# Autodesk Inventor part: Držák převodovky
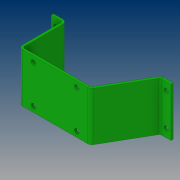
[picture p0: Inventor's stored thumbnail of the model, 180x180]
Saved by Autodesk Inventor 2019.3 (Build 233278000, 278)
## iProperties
Created: 2019-02
Part Number: Držák převodovky
Material: Ocel, pozinkovaná
Document SubType Name: Plech
Designer: B-hon
Density: 7.85 g/cm^3
Sheet Metal Rule: Výchozí_mm
Appearance: Tmavě zelená
Author: B-hon
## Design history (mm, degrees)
node "Plocha2"
  sketch "Náčrt1"
    geometry: L1 (0, 0)-(132.7, 0); L2 (132.7, 0)-(132.7, 90); L3 (132.7, 90)-(0, 90); L4 (0, 90)-(0, 0)
    constraints: 8 end point, 2 parallel, 1 horizontal, 1 perpendicular
    dimensions: "d0" = 132.7 distance of L3.end L2.end; "d1" = 90 distance of L2.end L1.end
node "Obruba5"
node "Obruba6"
node "Obruba7"
node "Obruba8"
sketch "Náčrt14"
  geometry: L1 (17, 90)-(0, 90) reference; L2 (0, 90)-(0, 0) reference; L3 (17, 0)-(0, 0) reference; 3 further points
  dimensions: "d117" = 15 distance from line of L1 point (8.5, 75); "d118" = 8.5 distance from line of L2 point (8.5, 75); "d119" = 15 distance from line of L3 point (8.5, 15); "d120" = 8.5 distance from line of L2 point (8.5, 15)
hole "Díra4" sketch "Náčrt14" at (8.5, 15), (8.5, 75) diameter "d121" = 8.5; stored, may be unused: countersink angle "d125" = 90 deg, drill point angle "d127" = 118 deg; dims "d122" = 6, "d123" = 4, "d124" = 2, "d126" = 4 (= Tloušťka)
sketch "Náčrt15"
  geometry: L1 (-17.381, 90)-(0, 90) reference; L2 (0, 0)-(0, 90) reference; L3 (-17.381, 0)-(0, 0) reference; 3 further points
  dimensions: "d128" = 15 distance from line of L1 point (-8.5, 75); "d129" = 8.5 distance from line of L2 point (-8.5, 75); "d130" = 8.5 distance from line of L2 point (-8.5, 15); "d131" = 15 distance from line of L3 point (-8.5, 15)
hole "Díra5" sketch "Náčrt15" at (-8.5, 75), (-8.5, 15) diameter "d132" = 8.5; stored, may be unused: countersink angle "d136" = 90 deg, drill point angle "d138" = 118 deg; dims "d133" = 6, "d134" = 4, "d135" = 2, "d137" = 4 (= Tloušťka)
sketch "Náčrt16"
  geometry: L1 (28, 80)-(108, 80); L2 (108, 80)-(108, 10); L3 (108, 10)-(28, 10); L4 (28, 10)-(28, 80); L5 (8, 90)-(128.081, 90) reference; L6 (8, 90)-(8, 0) reference; 5 further points
  constraints: 8 end point, 4 coincident, 2 parallel, 1 horizontal, 1 perpendicular
  dimensions: "d139" = 80 distance of L2.end L3.end; "d140" = 70 distance of L1.end L2.end; "d141" = 10 distance between parallel lines of L1 L5; "d142" = 20 distance between parallel lines of L6 L4
hole "Díra6" sketch "Náčrt16" at (28, 80), (108, 80), (108, 10), (28, 10) diameter "d143" = 8.5; stored, may be unused: countersink angle "d147" = 90 deg, drill point angle "d149" = 118 deg; dims "d144" = 6, "d145" = 4, "d146" = 2, "d148" = 4 (= Tloušťka)
node "Těleso2"
feature "Deska6" dims "d76" = 4 (= Tloušťka)
sketch "Náčrt10"
  geometry: L1 through (45, 0) direction (-1, 9.36e-35); L2 through (0, -43) direction (-3.91e-32, -1); L3 (0, -86)-(90, -86); L4 (90, -86)-(90, 0)
  constraints: 6 end point, 1 horizontal, 1 perpendicular, 1 vertical
feature "Deska7" dims "d76" = 4 (= Tloušťka), "d77" = 4 (= ŠířkaVýštipu), "d78" = 2 (= HloubkaVýštipu), "d79" = 8 (= MinimálníZbytek), "d80" = 4 (= PřechodovýPoloměr), "d81" = 86, "d82" = 90 deg, "d83" = 4 (= PoloměrOhybu), "d84" = 16 (= VelikostRohovéhoVýštipu), "d85" = 4 (= VelikostMezery), "d86" = 4 (= VelikostJacobihoPoloměru), "MezeraVystřižení" = 0.01
feature "Ohyb5" dims "d76" = 4 (= Tloušťka), "d77" = 4 (= ŠířkaVýštipu), "d78" = 2 (= HloubkaVýštipu), "d79" = 8 (= MinimálníZbytek), "d80" = 4 (= PřechodovýPoloměr), "d81" = 86, "d82" = 90 deg, "d83" = 4 (= PoloměrOhybu), "MezeraVystřižení" = 0.01
feature "Roh5" dims "d81" = 86, "d82" = 90 deg, "d84" = 16 (= VelikostRohovéhoVýštipu), "d85" = 4 (= VelikostMezery), "d86" = 4 (= VelikostJacobihoPoloměru)
sketch "Náčrt11"
  geometry: L1 through (0, 45) direction (-6.72e-16, -1); L2 through (12.5, 0) direction (1, -6.92e-16); L3 (25, 0)-(25, 90); L4 (25, 90)-(0, 90)
  constraints: 6 end point, 1 horizontal, 1 perpendicular, 1 vertical
feature "Deska8" dims "d76" = 4 (= Tloušťka), "d87" = 4 (= ŠířkaVýštipu), "d88" = 2 (= HloubkaVýštipu), "d89" = 8 (= MinimálníZbytek), "d90" = 4 (= PřechodovýPoloměr), "d91" = 25, "d92" = 90 deg, "d93" = 4 (= PoloměrOhybu), "d94" = 16 (= VelikostRohovéhoVýštipu), "d95" = 4 (= VelikostMezery), "d96" = 4 (= VelikostJacobihoPoloměru), "MezeraVystřižení" = 0.01
feature "Ohyb6" dims "d76" = 4 (= Tloušťka), "d87" = 4 (= ŠířkaVýštipu), "d88" = 2 (= HloubkaVýštipu), "d89" = 8 (= MinimálníZbytek), "d90" = 4 (= PřechodovýPoloměr), "d91" = 25, "d92" = 90 deg, "d93" = 4 (= PoloměrOhybu), "MezeraVystřižení" = 0.01
feature "Roh6" dims "d91" = 25, "d92" = 90 deg, "d94" = 16 (= VelikostRohovéhoVýštipu), "d95" = 4 (= VelikostMezery), "d96" = 4 (= VelikostJacobihoPoloměru)
sketch "Náčrt12"
  geometry: L1 through (45, 0) direction (-1, 0); L2 through (0, -48.498) direction (-4.07e-32, -1); L3 (0, -96.995)-(90, -96.995); L4 (90, -96.995)-(90, 0)
  constraints: 6 end point, 1 horizontal, 1 perpendicular, 1 vertical
feature "Deska9" dims "d76" = 4 (= Tloušťka), "d97" = 4 (= ŠířkaVýštipu), "d98" = 2 (= HloubkaVýštipu), "d99" = 8 (= MinimálníZbytek), "d100" = 4 (= PřechodovýPoloměr), "d101" = 96.995, "d102" = 60 deg, "d103" = 4 (= PoloměrOhybu), "d104" = 16 (= VelikostRohovéhoVýštipu), "d105" = 4 (= VelikostMezery), "d106" = 4 (= VelikostJacobihoPoloměru), "MezeraVystřižení" = 0.01
feature "Ohyb7" dims "d76" = 4 (= Tloušťka), "d97" = 4 (= ŠířkaVýštipu), "d98" = 2 (= HloubkaVýštipu), "d99" = 8 (= MinimálníZbytek), "d100" = 4 (= PřechodovýPoloměr), "d101" = 96.995, "d102" = 60 deg, "d103" = 4 (= PoloměrOhybu), "MezeraVystřižení" = 0.01
feature "Roh7" dims "d101" = 96.995, "d102" = 60 deg, "d104" = 16 (= VelikostRohovéhoVýštipu), "d105" = 4 (= VelikostMezery), "d106" = 4 (= VelikostJacobihoPoloměru)
sketch "Náčrt13"
  geometry: L1 through (0, -45) direction (3.95e-16, 1); L2 through (-11, 0) direction (-1, -1.9e-34); L3 (-22, 0)-(-22, -90); L4 (-22, -90)-(0, -90)
  constraints: 6 end point, 1 horizontal, 1 perpendicular, 1 vertical
feature "Deska10" dims "d76" = 4 (= Tloušťka), "d107" = 4 (= ŠířkaVýštipu), "d108" = 2 (= HloubkaVýštipu), "d109" = 8 (= MinimálníZbytek), "d110" = 4 (= PřechodovýPoloměr), "d111" = 22, "d112" = 60 deg, "d113" = 4 (= PoloměrOhybu), "d114" = 16 (= VelikostRohovéhoVýštipu), "d115" = 4 (= VelikostMezery), "d116" = 4 (= VelikostJacobihoPoloměru), "MezeraVystřižení" = 0.01
feature "Ohyb8" dims "d76" = 4 (= Tloušťka), "d107" = 4 (= ŠířkaVýštipu), "d108" = 2 (= HloubkaVýštipu), "d109" = 8 (= MinimálníZbytek), "d110" = 4 (= PřechodovýPoloměr), "d111" = 22, "d112" = 60 deg, "d113" = 4 (= PoloměrOhybu), "MezeraVystřižení" = 0.01
feature "Roh8" dims "d111" = 22, "d112" = 60 deg, "d114" = 16 (= VelikostRohovéhoVýštipu), "d115" = 4 (= VelikostMezery), "d116" = 4 (= VelikostJacobihoPoloměru)
other parameters: "Tloušťka" = 4, "KSoučinitel" = 4.4, "PoloměrOhybu" = 4 (= Tloušťka), "ŠířkaVýštipu" = 4 (= Tloušťka), "HloubkaVýštipu" = 2 (= 0.5 x Tloušťka), "VelikostRohovéhoVýštipu" = 16 (= 4 x Tloušťka), "MinimálníZbytek" = 8 (= 2 x Tloušťka), "PřechodovýPoloměr" = 4 (= PoloměrOhybu), "VelikostJacobihoPoloměru" = 4 (= PoloměrOhybu), "VelikostMezery" = 4 (= Tloušťka)
